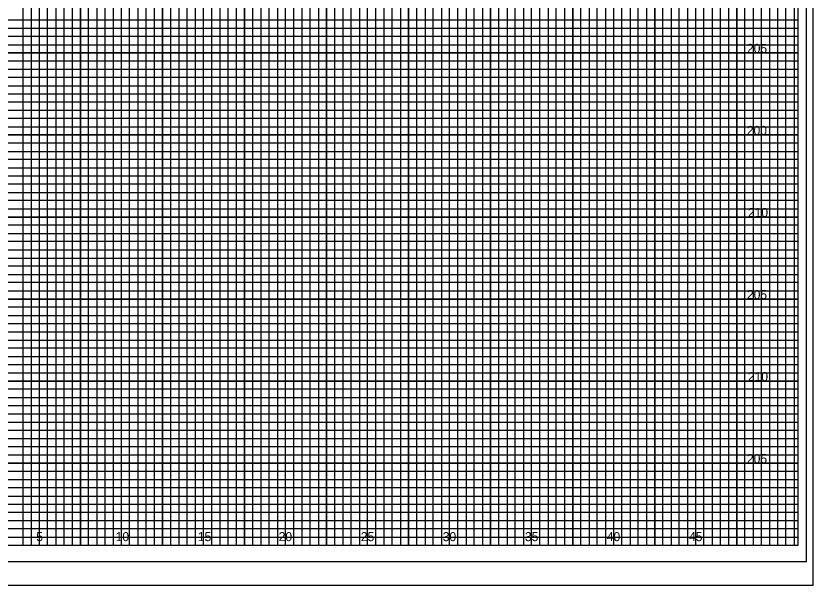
# Model space of a CAD drawing. Extents: x -4 to 103, y -2 to 138.
# Drawn here: x 54.82 to 103.4, y -2.43 to 32.25 of the extents above; entities that cross this region are included whole.
import ezdxf

# ---------------------------------------------------------------- set-up
doc = ezdxf.new("R2010")
doc.units = 0
for name, color, linetype in [('Exist XS Ground Line', 7, 'Continuous'), ('Old_Level_10', 7, 'Continuous'), ('Old_Level_16', 7, 'Continuous'), ('Old_Level_3', 7, 'Continuous'), ('Old_Level_5', 7, 'Continuous'), ('Old_Level_8', 7, 'Continuous'), ('Prop XS Dump Level', 7, 'Continuous'), ('Prop XS Elevation Labels', 7, 'Continuous'), ('Prop XS Finish Grade', 7, 'Continuous')]:
    doc.layers.add(name, color=color, linetype=linetype)

msp = doc.modelspace()

# ---------------------------------------------------------------- linework, layer by layer
at = {"layer": 'Exist XS Ground Line'}
msp.add_lwpolyline([(103, 66), (-2.8, 66), (-2.8, -1), (103, -1)], close=True, dxfattribs=at)
at = {"layer": 'Old_Level_10'}
for p, q in [((56.25, 0), (56.25, 65)), ((58.75, 0), (58.75, 65)), ((61.25, 0), (61.25, 65)), ((63.75, 0), (63.75, 65)), ((66.25, 0), (66.25, 65)), ((68.75, 0), (68.75, 65)), ((71.25, 0), (71.25, 65)), ((73.75, 0), (73.75, 65)), ((91.25, 0), (91.25, 63.425)), ((93.75, 0), (93.75, 63.425)), ((96.25, 0), (96.25, 63.425)), ((98.75, 0), (98.75, 63.425)), ((101.25, 0), (101.25, 63.425)), ((76.25, 0), (76.25, 62)), ((78.75, 0), (78.75, 62)), ((81.25, 0), (81.25, 62)), ((83.75, 0), (83.75, 62)), ((86.25, 0), (86.25, 62)), ((88.75, 0), (88.75, 62)), ((0, 30), (102.5, 30)), ((0, 27.5), (102.5, 27.5)), ((0, 25), (102.5, 25)), ((0, 22.5), (102.5, 22.5)), ((0, 20), (102.5, 20)), ((0, 17.5), (102.5, 17.5)), ((0, 15), (102.5, 15)), ((0, 12.5), (102.5, 12.5)), ((0, 10), (102.5, 10)), ((0, 7.5), (102.5, 7.5)), ((0, 5), (102.5, 5)), ((0, 2.5), (102.5, 2.5))]:
    msp.add_line(p, q, dxfattribs=at)
at = {"layer": 'Old_Level_3'}
msp.add_line((-3.5, -2.425), (103.4, -2.425), dxfattribs=at)
at = {"layer": 'Old_Level_5'}
msp.add_lwpolyline([(103.4, 67.4), (-3.5, 67.4), (-3.5, -2.425), (103.4, -2.425)], close=True, dxfattribs=at)
at = {"layer": 'Old_Level_8'}
for points in [[(56.25, 0), (56.25, 65)], [(58.75, 65), (58.75, 0), (61.25, 0), (61.25, 65)], [(63.75, 65), (63.75, 0), (66.25, 0), (66.25, 65)], [(68.75, 65), (68.75, 0), (71.25, 0), (71.25, 65)], [(73.75, 65), (73.75, 0), (76.25, 0), (76.25, 62)], [(88.75, 62), (88.75, 0), (91.25, 0), (91.25, 63.425)], [(93.75, 63.425), (93.75, 0), (96.25, 0), (96.25, 63.425)], [(98.75, 63.425), (98.75, 0), (101.25, 0), (101.25, 63.425)], [(78.75, 62), (78.75, 0), (81.25, 0), (81.25, 62)], [(83.75, 62), (83.75, 0), (86.25, 0), (86.25, 62)], [(0, 27.5), (102.5, 27.5), (102.5, 30), (0, 30)], [(0, 22.5), (102.5, 22.5), (102.5, 25), (0, 25)], [(0, 17.5), (102.5, 17.5), (102.5, 20), (0, 20)], [(0, 12.5), (102.5, 12.5), (102.5, 15), (0, 15)], [(0, 7.5), (102.5, 7.5), (102.5, 10), (0, 10)], [(0, 2.5), (102.5, 2.5), (102.5, 5), (0, 5)]]:
    msp.add_lwpolyline(points, dxfattribs=at)
at = {"layer": 'Prop XS Elevation Labels'}
msp.add_lwpolyline([(102.5, 65), (0, 65), (0, 0), (102.5, 0)], close=True, dxfattribs=at)
at = {"layer": 'Prop XS Finish Grade'}
for points in [[(54.75, 0), (55.25, 0), (55.25, 65)], [(55.75, 65), (55.75, 0), (56.75, 0), (56.75, 65)], [(57.25, 65), (57.25, 0), (57.75, 0), (57.75, 65)], [(58.25, 65), (58.25, 0), (59.25, 0), (59.25, 65)], [(59.75, 65), (59.75, 0), (60.25, 0), (60.25, 65)], [(60.75, 65), (60.75, 0), (61.75, 0), (61.75, 65)], [(62.25, 65), (62.25, 0), (62.75, 0), (62.75, 65)], [(63.25, 65), (63.25, 0), (64.25, 0), (64.25, 65)], [(64.75, 65), (64.75, 0), (65.25, 0), (65.25, 65)], [(65.75, 65), (65.75, 0), (66.75, 0), (66.75, 65)], [(67.25, 65), (67.25, 0), (67.75, 0), (67.75, 65)], [(68.25, 65), (68.25, 0), (69.25, 0), (69.25, 65)], [(69.75, 65), (69.75, 0), (70.25, 0), (70.25, 65)], [(70.75, 65), (70.75, 0), (71.75, 0), (71.75, 65)], [(72.25, 65), (72.25, 0), (72.75, 0), (72.75, 65)], [(73.25, 65), (73.25, 0), (74.25, 0), (74.25, 62)], [(89.75, 62), (89.75, 0), (90.25, 0), (90.25, 63.425)], [(90.75, 63.425), (90.75, 0), (91.75, 0), (91.75, 63.425)], [(92.25, 63.425), (92.25, 0), (92.75, 0), (92.75, 63.425)], [(93.25, 63.425), (93.25, 0), (94.25, 0), (94.25, 63.425)], [(94.75, 63.425), (94.75, 0), (95.25, 0), (95.25, 63.425)], [(95.75, 63.425), (95.75, 0), (96.75, 0), (96.75, 63.425)], [(97.25, 63.425), (97.25, 0), (97.75, 0), (97.75, 63.425)], [(98.25, 63.425), (98.25, 0), (99.25, 0), (99.25, 63.425)], [(99.75, 63.425), (99.75, 0), (100.25, 0), (100.25, 63.425)], [(100.25, 63.425), (100.75, 63.425), (100.75, 0), (101.75, 0), (101.75, 63.425), (102.25, 63.425), (102.25, 0)], [(74.75, 62), (74.75, 0), (75.25, 0), (75.25, 62)], [(75.75, 62), (75.75, 0), (76.75, 0), (76.75, 62)], [(77.25, 62), (77.25, 0), (77.75, 0), (77.75, 62)], [(78.25, 62), (78.25, 0), (79.25, 0), (79.25, 62)], [(79.75, 62), (79.75, 0), (80.25, 0), (80.25, 62)], [(80.75, 62), (80.75, 0), (81.75, 0), (81.75, 62)], [(82.25, 62), (82.25, 0), (82.75, 0), (82.75, 62)], [(83.25, 62), (83.25, 0), (84.25, 0), (84.25, 62)], [(84.75, 62), (84.75, 0), (85.25, 0), (85.25, 62)], [(85.75, 62), (85.75, 0), (86.75, 0), (86.75, 62)], [(87.25, 62), (87.25, 0), (87.75, 0), (87.75, 62)], [(88.25, 62), (88.25, 0), (89.25, 0), (89.25, 62)], [(0, 31.5), (102.5, 31.5), (102.5, 32), (0, 32)], [(0, 30.5), (102.5, 30.5), (102.5, 31), (0, 31)], [(0, 29), (102.5, 29), (102.5, 29.5), (0, 29.5)], [(0, 28), (102.5, 28), (102.5, 28.5), (0, 28.5)], [(0, 26.5), (102.5, 26.5), (102.5, 27), (0, 27)], [(0, 25.5), (102.5, 25.5), (102.5, 26), (0, 26)], [(0, 24), (102.5, 24), (102.5, 24.5), (0, 24.5)], [(0, 23), (102.5, 23), (102.5, 23.5), (0, 23.5)], [(0, 21.5), (102.5, 21.5), (102.5, 22), (0, 22)], [(0, 20.5), (102.5, 20.5), (102.5, 21), (0, 21)], [(0, 19), (102.5, 19), (102.5, 19.5), (0, 19.5)], [(0, 18), (102.5, 18), (102.5, 18.5), (0, 18.5)], [(0, 16.5), (102.5, 16.5), (102.5, 17), (0, 17)], [(0, 15.5), (102.5, 15.5), (102.5, 16), (0, 16)], [(0, 14), (102.5, 14), (102.5, 14.5), (0, 14.5)], [(0, 13), (102.5, 13), (102.5, 13.5), (0, 13.5)], [(0, 11.5), (102.5, 11.5), (102.5, 12), (0, 12)], [(0, 10.5), (102.5, 10.5), (102.5, 11), (0, 11)], [(0, 9), (102.5, 9), (102.5, 9.5), (0, 9.5)], [(0, 8), (102.5, 8), (102.5, 8.5), (0, 8.5)], [(0, 6.5), (102.5, 6.5), (102.5, 7), (0, 7)], [(0, 5.5), (102.5, 5.5), (102.5, 6), (0, 6)], [(0, 4), (102.5, 4), (102.5, 4.5), (0, 4.5)], [(0, 3), (102.5, 3), (102.5, 3.5), (0, 3.5)], [(0, 1.5), (102.5, 1.5), (102.5, 2), (0, 2)], [(0, 0.5), (102.5, 0.5), (102.5, 1), (0, 1)]]:
    msp.add_lwpolyline(points, dxfattribs=at)

# ---------------------------------------------------------------- texts
at = {"layer": 'Old_Level_16'}
for s, p in [('5', (56.057, 0.25)), ('10', (60.897, 0.25)), ('15', (65.906, 0.25)), ('20', (70.831, 0.25)), ('25', (75.84, 0.25)), ('30', (80.831, 0.25)), ('35', (85.84, 0.25)), ('40', (90.831, 0.25)), ('45', (95.84, 0.25))]:
    msp.add_text(s, height=0.55, dxfattribs=at).set_placement(p)
at = {"layer": 'Prop XS Dump Level'}
for s, p in [('205', (99.372, 30)), ('200', (99.364, 25)), ('210', (99.43, 20)), ('205', (99.372, 15)), ('210', (99.43, 10)), ('205', (99.372, 5))]:
    msp.add_text(s, height=0.55, dxfattribs=at).set_placement(p)

doc.saveas('drawing.dxf')
